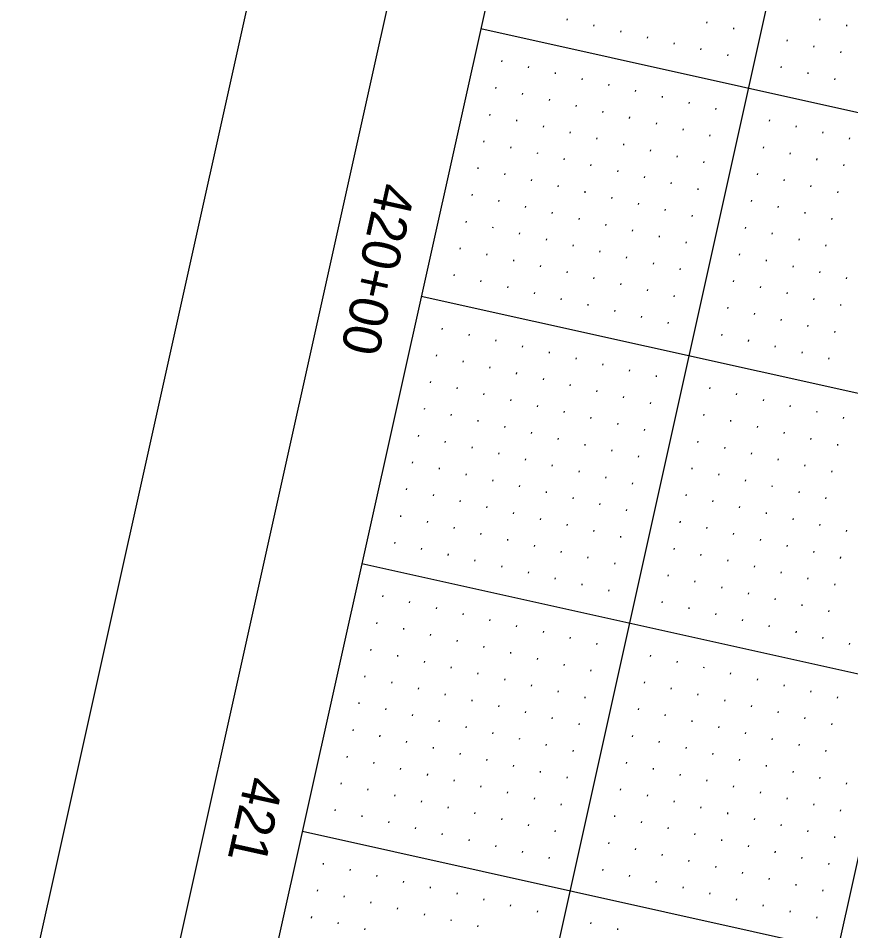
# Model space of a CAD drawing. Extents: x 2149268 to 2150830, y 142155 to 144285.
# Drawn here: x 2149420.1 to 2149571.9, y 142846.7 to 143013.1 of the extents above; entities that cross this region are included whole.
import ezdxf

# ---------------------------------------------------------------- set-up
doc = ezdxf.new("R2010")
doc.units = 0
for name, color, linetype in [('SHT_Plan_Profile_Sheet_Sta_Txt', 7, 'Continuous'), ('SHT_Plot_Shape_Half', 7, 'Continuous'), ('SHT_Profile_Grid_Major', 7, 'Continuous'), ('SHT_Profile_Grid_Minor', 7, 'Continuous'), ('SHT_Sheet_Border', 7, 'Continuous')]:
    doc.layers.add(name, color=color, linetype=linetype)

msp = doc.modelspace()

# ---------------------------------------------------------------- linework, layer by layer
at = {"layer": 'SHT_Plot_Shape_Half'}
msp.add_lwpolyline([(2150772.24, 143840.86), (2150403.25, 142181.39), (2149329.47, 142420.15), (2149698.47, 144079.62)], close=True, dxfattribs=at)
at = {"layer": 'SHT_Profile_Grid_Major'}
for p, q in [((2149767.6, 143964.37), (2149425.74, 142426.92)), ((2149816.41, 143953.52), (2149474.54, 142416.07)), ((2149504.45, 143011.27), (2149992.53, 142902.74)), ((2149493.59, 142962.46), (2149981.67, 142853.93)), ((2149482.74, 142913.65), (2149970.82, 142805.12)), ((2149471.89, 142864.84), (2149959.97, 142756.31))]:
    msp.add_line(p, q, dxfattribs=at)
at = {"layer": 'SHT_Profile_Grid_Minor'}
for p, q in [((2149520.2, 143013.01), (2149520.15, 143012.77)), ((2149525.08, 143011.93), (2149525.03, 143011.68)), ((2149545.69, 143012.47), (2149545.64, 143012.22)), ((2149566.3, 143013.01), (2149566.25, 143012.76)), ((2149571.18, 143011.92), (2149571.13, 143011.68)), ((2149529.96, 143010.84), (2149529.91, 143010.6)), ((2149550.57, 143011.38), (2149550.52, 143011.14)), ((2149534.84, 143009.76), (2149534.79, 143009.51)), ((2149539.73, 143008.67), (2149539.67, 143008.43)), ((2149560.33, 143009.21), (2149560.28, 143008.97)), ((2149544.61, 143007.59), (2149544.55, 143007.34)), ((2149565.21, 143008.13), (2149565.16, 143007.88)), ((2149570.1, 143007.04), (2149570.04, 143006.8)), ((2149508.27, 143005.42), (2149508.22, 143005.18)), ((2149549.49, 143006.5), (2149549.43, 143006.26)), ((2149513.15, 143004.34), (2149513.1, 143004.09)), ((2149559.25, 143004.33), (2149559.19, 143004.09)), ((2149518.03, 143003.25), (2149517.98, 143003.01)), ((2149522.91, 143002.17), (2149522.86, 143001.92)), ((2149564.13, 143003.25), (2149564.08, 143003)), ((2149569.01, 143002.16), (2149568.96, 143001.92)), ((2149507.18, 143000.54), (2149507.13, 143000.3)), ((2149527.79, 143001.08), (2149527.74, 143000.84)), ((2149512.07, 142999.46), (2149512.01, 142999.21)), ((2149532.67, 143000), (2149532.62, 142999.75)), ((2149537.55, 142998.91), (2149537.5, 142998.67)), ((2149516.95, 142998.37), (2149516.89, 142998.13)), ((2149521.83, 142997.29), (2149521.77, 142997.04)), ((2149542.44, 142997.83), (2149542.38, 142997.58)), ((2149506.1, 142995.66), (2149506.05, 142995.42)), ((2149526.71, 142996.2), (2149526.65, 142995.96)), ((2149547.32, 142996.74), (2149547.26, 142996.5)), ((2149510.98, 142994.58), (2149510.93, 142994.33)), ((2149515.86, 142993.49), (2149515.81, 142993.25)), ((2149531.59, 142995.12), (2149531.53, 142994.87)), ((2149536.47, 142994.03), (2149536.42, 142993.79)), ((2149557.08, 142994.57), (2149557.02, 142994.33)), ((2149520.74, 142992.4), (2149520.69, 142992.16)), ((2149541.35, 142992.94), (2149541.3, 142992.7)), ((2149546.23, 142991.86), (2149546.18, 142991.62)), ((2149561.96, 142993.48), (2149561.9, 142993.24)), ((2149566.84, 142992.4), (2149566.79, 142992.15)), ((2149505.01, 142990.78), (2149504.96, 142990.54)), ((2149525.62, 142991.32), (2149525.57, 142991.08)), ((2149530.5, 142990.23), (2149530.45, 142989.99)), ((2149571.72, 142991.31), (2149571.67, 142991.07)), ((2149509.9, 142989.69), (2149509.84, 142989.45)), ((2149514.78, 142988.61), (2149514.72, 142988.37)), ((2149535.38, 142989.15), (2149535.33, 142988.9)), ((2149555.99, 142989.69), (2149555.94, 142989.44)), ((2149560.87, 142988.6), (2149560.82, 142988.36)), ((2149519.66, 142987.52), (2149519.6, 142987.28)), ((2149540.27, 142988.06), (2149540.21, 142987.82)), ((2149545.15, 142986.98), (2149545.09, 142986.73)), ((2149565.75, 142987.52), (2149565.7, 142987.27)), ((2149503.93, 142985.9), (2149503.87, 142985.66)), ((2149524.54, 142986.44), (2149524.48, 142986.19)), ((2149529.42, 142985.35), (2149529.36, 142985.11)), ((2149570.64, 142986.43), (2149570.58, 142986.19)), ((2149508.81, 142984.81), (2149508.76, 142984.57)), ((2149513.69, 142983.73), (2149513.64, 142983.48)), ((2149534.3, 142984.27), (2149534.24, 142984.02)), ((2149554.91, 142984.81), (2149554.85, 142984.56)), ((2149559.79, 142983.72), (2149559.73, 142983.48)), ((2149518.57, 142982.64), (2149518.52, 142982.4)), ((2149539.18, 142983.18), (2149539.13, 142982.94)), ((2149544.06, 142982.1), (2149544.01, 142981.85)), ((2149564.67, 142982.64), (2149564.61, 142982.39)), ((2149502.84, 142981.02), (2149502.79, 142980.77)), ((2149523.45, 142981.56), (2149523.4, 142981.31)), ((2149528.33, 142980.47), (2149528.28, 142980.23)), ((2149569.55, 142981.55), (2149569.5, 142981.31)), ((2149507.72, 142979.93), (2149507.67, 142979.69)), ((2149512.61, 142978.85), (2149512.55, 142978.6)), ((2149533.21, 142979.39), (2149533.16, 142979.14)), ((2149553.82, 142979.93), (2149553.77, 142979.68)), ((2149558.7, 142978.84), (2149558.65, 142978.6)), ((2149517.49, 142977.76), (2149517.43, 142977.52)), ((2149538.09, 142978.3), (2149538.04, 142978.06)), ((2149542.98, 142977.22), (2149542.92, 142976.97)), ((2149563.58, 142977.76), (2149563.53, 142977.51)), ((2149501.76, 142976.14), (2149501.7, 142975.89)), ((2149522.37, 142976.68), (2149522.31, 142976.43)), ((2149527.25, 142975.59), (2149527.19, 142975.35)), ((2149568.46, 142976.67), (2149568.41, 142976.43)), ((2149506.64, 142975.05), (2149506.59, 142974.81)), ((2149511.52, 142973.97), (2149511.47, 142973.72)), ((2149532.13, 142974.51), (2149532.07, 142974.26)), ((2149552.74, 142975.05), (2149552.68, 142974.8)), ((2149557.62, 142973.96), (2149557.56, 142973.72)), ((2149516.4, 142972.88), (2149516.35, 142972.64)), ((2149537.01, 142973.42), (2149536.96, 142973.18)), ((2149541.89, 142972.34), (2149541.84, 142972.09)), ((2149562.5, 142972.88), (2149562.44, 142972.63)), ((2149500.67, 142971.26), (2149500.62, 142971.01)), ((2149521.28, 142971.8), (2149521.23, 142971.55)), ((2149526.16, 142970.71), (2149526.11, 142970.47)), ((2149567.38, 142971.79), (2149567.33, 142971.55)), ((2149505.55, 142970.17), (2149505.5, 142969.93)), ((2149510.43, 142969.09), (2149510.38, 142968.84)), ((2149531.04, 142969.63), (2149530.99, 142969.38)), ((2149535.92, 142968.54), (2149535.87, 142968.3)), ((2149551.65, 142970.17), (2149551.6, 142969.92)), ((2149556.53, 142969.08), (2149556.48, 142968.84)), ((2149515.32, 142968), (2149515.26, 142967.76)), ((2149520.2, 142966.92), (2149520.14, 142966.67)), ((2149540.8, 142967.46), (2149540.75, 142967.21)), ((2149561.41, 142967.99), (2149561.36, 142967.75)), ((2149566.29, 142966.91), (2149566.24, 142966.67)), ((2149499.59, 142966.38), (2149499.53, 142966.13)), ((2149504.47, 142965.29), (2149504.41, 142965.05)), ((2149525.08, 142965.83), (2149525.02, 142965.59)), ((2149550.57, 142965.28), (2149550.51, 142965.04)), ((2149571.17, 142965.82), (2149571.12, 142965.58)), ((2149509.35, 142964.21), (2149509.3, 142963.96)), ((2149529.96, 142964.75), (2149529.9, 142964.5)), ((2149534.84, 142963.66), (2149534.78, 142963.42)), ((2149555.45, 142964.2), (2149555.39, 142963.96)), ((2149514.23, 142963.12), (2149514.18, 142962.88)), ((2149519.11, 142962.03), (2149519.06, 142961.79)), ((2149539.72, 142962.57), (2149539.67, 142962.33)), ((2149560.33, 142963.11), (2149560.27, 142962.87)), ((2149565.21, 142962.03), (2149565.15, 142961.78)), ((2149523.99, 142960.95), (2149523.94, 142960.71)), ((2149549.48, 142960.4), (2149549.43, 142960.16)), ((2149570.09, 142960.94), (2149570.04, 142960.7)), ((2149528.87, 142959.86), (2149528.82, 142959.62)), ((2149533.75, 142958.78), (2149533.7, 142958.53)), ((2149554.36, 142959.32), (2149554.31, 142959.07)), ((2149538.63, 142957.69), (2149538.58, 142957.45)), ((2149559.24, 142958.23), (2149559.19, 142957.99)), ((2149564.12, 142957.15), (2149564.07, 142956.9)), ((2149497.42, 142956.61), (2149497.36, 142956.37)), ((2149502.3, 142955.53), (2149502.24, 142955.28)), ((2149548.4, 142955.52), (2149548.34, 142955.28)), ((2149569, 142956.06), (2149568.95, 142955.82)), ((2149507.18, 142954.44), (2149507.12, 142954.2)), ((2149553.28, 142954.44), (2149553.22, 142954.19)), ((2149512.06, 142953.36), (2149512.01, 142953.11)), ((2149516.94, 142952.27), (2149516.89, 142952.03)), ((2149558.16, 142953.35), (2149558.1, 142953.11)), ((2149563.04, 142952.27), (2149562.98, 142952.02)), ((2149496.33, 142951.73), (2149496.28, 142951.49)), ((2149501.21, 142950.65), (2149501.16, 142950.4)), ((2149521.82, 142951.19), (2149521.77, 142950.94)), ((2149567.92, 142951.18), (2149567.86, 142950.94)), ((2149506.09, 142949.56), (2149506.04, 142949.32)), ((2149526.7, 142950.1), (2149526.65, 142949.86)), ((2149531.58, 142949.02), (2149531.53, 142948.77)), ((2149510.97, 142948.48), (2149510.92, 142948.23)), ((2149515.86, 142947.39), (2149515.8, 142947.15)), ((2149536.46, 142947.93), (2149536.41, 142947.69)), ((2149495.25, 142946.85), (2149495.19, 142946.61)), ((2149500.13, 142945.77), (2149500.07, 142945.52)), ((2149520.74, 142946.31), (2149520.68, 142946.06)), ((2149525.62, 142945.22), (2149525.56, 142944.98)), ((2149546.23, 142945.76), (2149546.17, 142945.52)), ((2149505.01, 142944.68), (2149504.95, 142944.44)), ((2149509.89, 142943.6), (2149509.83, 142943.35)), ((2149530.5, 142944.14), (2149530.44, 142943.89)), ((2149551.11, 142944.68), (2149551.05, 142944.43)), ((2149555.99, 142943.59), (2149555.93, 142943.35)), ((2149494.16, 142941.97), (2149494.11, 142941.73)), ((2149514.77, 142942.51), (2149514.72, 142942.27)), ((2149535.38, 142943.05), (2149535.32, 142942.81)), ((2149560.87, 142942.51), (2149560.81, 142942.26)), ((2149499.04, 142940.89), (2149498.99, 142940.64)), ((2149519.65, 142941.43), (2149519.6, 142941.18)), ((2149524.53, 142940.34), (2149524.48, 142940.1)), ((2149545.14, 142940.88), (2149545.09, 142940.64)), ((2149565.75, 142941.42), (2149565.69, 142941.18)), ((2149570.63, 142940.34), (2149570.57, 142940.09)), ((2149503.92, 142939.8), (2149503.87, 142939.56)), ((2149508.8, 142938.72), (2149508.75, 142938.47)), ((2149529.41, 142939.26), (2149529.36, 142939.01)), ((2149550.02, 142939.8), (2149549.97, 142939.55)), ((2149554.9, 142938.71), (2149554.85, 142938.47)), ((2149493.08, 142937.09), (2149493.02, 142936.85)), ((2149513.68, 142937.63), (2149513.63, 142937.39)), ((2149534.29, 142938.17), (2149534.24, 142937.93)), ((2149559.78, 142937.62), (2149559.73, 142937.38)), ((2149497.96, 142936.01), (2149497.9, 142935.76)), ((2149518.57, 142936.55), (2149518.51, 142936.3)), ((2149523.45, 142935.46), (2149523.39, 142935.22)), ((2149544.05, 142936), (2149544, 142935.76)), ((2149564.66, 142936.54), (2149564.61, 142936.3)), ((2149569.54, 142935.45), (2149569.49, 142935.21)), ((2149502.84, 142934.92), (2149502.78, 142934.68)), ((2149507.72, 142933.84), (2149507.66, 142933.59)), ((2149528.33, 142934.37), (2149528.27, 142934.13)), ((2149548.94, 142934.91), (2149548.88, 142934.67)), ((2149553.82, 142933.83), (2149553.76, 142933.59)), ((2149491.99, 142932.21), (2149491.94, 142931.97)), ((2149512.6, 142932.75), (2149512.55, 142932.51)), ((2149533.21, 142933.29), (2149533.15, 142933.05)), ((2149558.7, 142932.74), (2149558.64, 142932.5)), ((2149496.87, 142931.13), (2149496.82, 142930.88)), ((2149517.48, 142931.66), (2149517.43, 142931.42)), ((2149522.36, 142930.58), (2149522.31, 142930.34)), ((2149542.97, 142931.12), (2149542.92, 142930.88)), ((2149563.58, 142931.66), (2149563.52, 142931.41)), ((2149568.46, 142930.57), (2149568.4, 142930.33)), ((2149501.75, 142930.04), (2149501.7, 142929.8)), ((2149506.63, 142928.95), (2149506.58, 142928.71)), ((2149527.24, 142929.49), (2149527.19, 142929.25)), ((2149547.85, 142930.03), (2149547.8, 142929.79)), ((2149552.73, 142928.95), (2149552.68, 142928.7)), ((2149490.91, 142927.33), (2149490.85, 142927.09)), ((2149511.51, 142927.87), (2149511.46, 142927.63)), ((2149532.12, 142928.41), (2149532.07, 142928.16)), ((2149557.61, 142927.86), (2149557.56, 142927.62)), ((2149495.79, 142926.24), (2149495.73, 142926)), ((2149516.39, 142926.78), (2149516.34, 142926.54)), ((2149521.28, 142925.7), (2149521.22, 142925.45)), ((2149541.88, 142926.24), (2149541.83, 142925.99)), ((2149562.49, 142926.78), (2149562.44, 142926.53)), ((2149567.37, 142925.69), (2149567.32, 142925.45)), ((2149500.67, 142925.16), (2149500.61, 142924.91)), ((2149505.55, 142924.07), (2149505.49, 142923.83)), ((2149526.16, 142924.61), (2149526.1, 142924.37)), ((2149546.76, 142925.15), (2149546.71, 142924.91)), ((2149551.65, 142924.07), (2149551.59, 142923.82)), ((2149489.82, 142922.45), (2149489.77, 142922.2)), ((2149510.43, 142922.99), (2149510.37, 142922.74)), ((2149531.04, 142923.53), (2149530.98, 142923.28)), ((2149556.53, 142922.98), (2149556.47, 142922.74)), ((2149494.7, 142921.36), (2149494.65, 142921.12)), ((2149499.58, 142920.28), (2149499.53, 142920.03)), ((2149515.31, 142921.9), (2149515.26, 142921.66)), ((2149520.19, 142920.82), (2149520.14, 142920.57)), ((2149540.8, 142921.36), (2149540.74, 142921.11)), ((2149545.68, 142920.27), (2149545.63, 142920.03)), ((2149561.41, 142921.9), (2149561.35, 142921.65)), ((2149566.29, 142920.81), (2149566.23, 142920.57)), ((2149504.46, 142919.19), (2149504.41, 142918.95)), ((2149525.07, 142919.73), (2149525.02, 142919.49)), ((2149529.95, 142918.65), (2149529.9, 142918.4)), ((2149550.56, 142919.19), (2149550.51, 142918.94)), ((2149571.17, 142919.73), (2149571.11, 142919.48)), ((2149488.74, 142917.57), (2149488.68, 142917.32)), ((2149509.34, 142918.11), (2149509.29, 142917.86)), ((2149514.22, 142917.02), (2149514.17, 142916.78)), ((2149555.44, 142918.1), (2149555.39, 142917.86)), ((2149560.32, 142917.02), (2149560.27, 142916.77)), ((2149493.62, 142916.48), (2149493.56, 142916.24)), ((2149498.5, 142915.4), (2149498.44, 142915.15)), ((2149519.11, 142915.94), (2149519.05, 142915.69)), ((2149539.71, 142916.48), (2149539.66, 142916.23)), ((2149544.59, 142915.39), (2149544.54, 142915.15)), ((2149565.2, 142915.93), (2149565.15, 142915.69)), ((2149503.38, 142914.31), (2149503.32, 142914.07)), ((2149523.99, 142914.85), (2149523.93, 142914.61)), ((2149528.87, 142913.77), (2149528.81, 142913.52)), ((2149549.48, 142914.31), (2149549.42, 142914.06)), ((2149570.08, 142914.85), (2149570.03, 142914.6)), ((2149508.26, 142913.23), (2149508.2, 142912.98)), ((2149513.14, 142912.14), (2149513.08, 142911.9)), ((2149554.36, 142913.22), (2149554.3, 142912.98)), ((2149559.24, 142912.14), (2149559.18, 142911.89)), ((2149518.02, 142911.06), (2149517.97, 142910.81)), ((2149538.63, 142911.6), (2149538.57, 142911.35)), ((2149543.51, 142910.51), (2149543.45, 142910.27)), ((2149564.12, 142911.05), (2149564.06, 142910.81)), ((2149522.9, 142909.97), (2149522.85, 142909.73)), ((2149527.78, 142908.89), (2149527.73, 142908.64)), ((2149548.39, 142909.43), (2149548.34, 142909.18)), ((2149569, 142909.97), (2149568.94, 142909.72)), ((2149486.56, 142907.81), (2149486.51, 142907.56)), ((2149553.27, 142908.34), (2149553.22, 142908.1)), ((2149558.15, 142907.25), (2149558.1, 142907.01)), ((2149491.45, 142906.72), (2149491.39, 142906.48)), ((2149496.33, 142905.64), (2149496.27, 142905.39)), ((2149537.54, 142906.72), (2149537.49, 142906.47)), ((2149542.42, 142905.63), (2149542.37, 142905.39)), ((2149563.03, 142906.17), (2149562.98, 142905.93)), ((2149501.21, 142904.55), (2149501.15, 142904.31)), ((2149547.3, 142904.54), (2149547.25, 142904.3)), ((2149567.91, 142905.08), (2149567.86, 142904.84)), ((2149485.48, 142902.93), (2149485.43, 142902.68)), ((2149506.09, 142903.47), (2149506.03, 142903.22)), ((2149510.97, 142902.38), (2149510.91, 142902.14)), ((2149552.19, 142903.46), (2149552.13, 142903.22)), ((2149557.07, 142902.37), (2149557.01, 142902.13)), ((2149490.36, 142901.84), (2149490.31, 142901.6)), ((2149495.24, 142900.75), (2149495.19, 142900.51)), ((2149515.85, 142901.29), (2149515.8, 142901.05)), ((2149561.95, 142901.29), (2149561.89, 142901.04)), ((2149500.12, 142899.67), (2149500.07, 142899.43)), ((2149520.73, 142900.21), (2149520.68, 142899.97)), ((2149525.61, 142899.12), (2149525.56, 142898.88)), ((2149566.83, 142900.2), (2149566.77, 142899.96)), ((2149571.71, 142899.12), (2149571.65, 142898.87)), ((2149484.39, 142898.04), (2149484.34, 142897.8)), ((2149489.27, 142896.96), (2149489.22, 142896.72)), ((2149505, 142898.58), (2149504.95, 142898.34)), ((2149509.88, 142897.5), (2149509.83, 142897.26)), ((2149535.37, 142896.95), (2149535.32, 142896.71)), ((2149494.16, 142895.87), (2149494.1, 142895.63)), ((2149514.76, 142896.41), (2149514.71, 142896.17)), ((2149519.64, 142895.33), (2149519.59, 142895.08)), ((2149540.25, 142895.87), (2149540.2, 142895.62)), ((2149499.04, 142894.79), (2149498.98, 142894.54)), ((2149503.92, 142893.7), (2149503.86, 142893.46)), ((2149524.53, 142894.24), (2149524.47, 142894)), ((2149545.13, 142894.78), (2149545.08, 142894.54)), ((2149550.01, 142893.7), (2149549.96, 142893.45)), ((2149483.31, 142893.16), (2149483.25, 142892.92)), ((2149488.19, 142892.08), (2149488.14, 142891.83)), ((2149508.8, 142892.62), (2149508.74, 142892.37)), ((2149534.29, 142892.07), (2149534.23, 142891.83)), ((2149554.9, 142892.61), (2149554.84, 142892.37)), ((2149493.07, 142890.99), (2149493.02, 142890.75)), ((2149513.68, 142891.53), (2149513.62, 142891.29)), ((2149518.56, 142890.45), (2149518.51, 142890.2)), ((2149539.17, 142890.99), (2149539.11, 142890.74)), ((2149559.78, 142891.53), (2149559.72, 142891.28)), ((2149564.66, 142890.44), (2149564.6, 142890.2)), ((2149497.95, 142889.91), (2149497.9, 142889.66)), ((2149502.83, 142888.82), (2149502.78, 142888.58)), ((2149523.44, 142889.36), (2149523.39, 142889.12)), ((2149544.05, 142889.9), (2149543.99, 142889.66)), ((2149548.93, 142888.82), (2149548.88, 142888.57)), ((2149569.54, 142889.36), (2149569.48, 142889.11)), ((2149482.22, 142888.28), (2149482.17, 142888.04)), ((2149487.1, 142887.2), (2149487.05, 142886.95)), ((2149507.71, 142887.74), (2149507.66, 142887.49)), ((2149533.2, 142887.19), (2149533.15, 142886.95)), ((2149553.81, 142887.73), (2149553.76, 142887.49)), ((2149491.99, 142886.11), (2149491.93, 142885.87)), ((2149512.59, 142886.65), (2149512.54, 142886.41)), ((2149517.47, 142885.57), (2149517.42, 142885.32)), ((2149538.08, 142886.11), (2149538.03, 142885.86)), ((2149558.69, 142886.65), (2149558.64, 142886.4)), ((2149563.57, 142885.56), (2149563.52, 142885.32)), ((2149496.87, 142885.03), (2149496.81, 142884.78)), ((2149501.75, 142883.94), (2149501.69, 142883.7)), ((2149522.36, 142884.48), (2149522.3, 142884.24)), ((2149542.96, 142885.02), (2149542.91, 142884.78)), ((2149547.84, 142883.94), (2149547.79, 142883.69)), ((2149568.45, 142884.48), (2149568.4, 142884.23)), ((2149481.14, 142883.4), (2149481.08, 142883.16)), ((2149486.02, 142882.32), (2149485.96, 142882.07)), ((2149506.63, 142882.86), (2149506.57, 142882.61)), ((2149532.12, 142882.31), (2149532.06, 142882.07)), ((2149552.73, 142882.85), (2149552.67, 142882.61)), ((2149490.9, 142881.23), (2149490.85, 142880.99)), ((2149511.51, 142881.77), (2149511.45, 142881.53)), ((2149516.39, 142880.69), (2149516.33, 142880.44)), ((2149537, 142881.23), (2149536.94, 142880.98)), ((2149557.61, 142881.77), (2149557.55, 142881.52)), ((2149562.49, 142880.68), (2149562.43, 142880.44)), ((2149495.78, 142880.15), (2149495.73, 142879.9)), ((2149500.66, 142879.06), (2149500.61, 142878.82)), ((2149521.27, 142879.6), (2149521.22, 142879.36)), ((2149541.88, 142880.14), (2149541.82, 142879.9)), ((2149546.76, 142879.06), (2149546.7, 142878.81)), ((2149567.37, 142879.6), (2149567.31, 142879.35)), ((2149480.05, 142878.52), (2149480, 142878.28)), ((2149484.93, 142877.44), (2149484.88, 142877.19)), ((2149505.54, 142877.98), (2149505.49, 142877.73)), ((2149531.03, 142877.43), (2149530.98, 142877.19)), ((2149551.64, 142877.97), (2149551.59, 142877.73)), ((2149489.81, 142876.35), (2149489.76, 142876.11)), ((2149510.42, 142876.89), (2149510.37, 142876.65)), ((2149515.3, 142875.81), (2149515.25, 142875.56)), ((2149535.91, 142876.35), (2149535.86, 142876.1)), ((2149556.52, 142876.88), (2149556.47, 142876.64)), ((2149561.4, 142875.8), (2149561.35, 142875.56)), ((2149478.97, 142873.64), (2149478.91, 142873.4)), ((2149494.7, 142875.27), (2149494.64, 142875.02)), ((2149499.58, 142874.18), (2149499.52, 142873.94)), ((2149520.18, 142874.72), (2149520.13, 142874.48)), ((2149540.79, 142875.26), (2149540.74, 142875.02)), ((2149545.67, 142874.17), (2149545.62, 142873.93)), ((2149566.28, 142874.71), (2149566.23, 142874.47)), ((2149483.85, 142872.56), (2149483.79, 142872.31)), ((2149504.46, 142873.1), (2149504.4, 142872.85)), ((2149509.34, 142872.01), (2149509.28, 142871.77)), ((2149529.95, 142872.55), (2149529.89, 142872.31)), ((2149550.55, 142873.09), (2149550.5, 142872.85)), ((2149555.44, 142872), (2149555.38, 142871.76)), ((2149571.16, 142873.63), (2149571.11, 142873.38)), ((2149488.73, 142871.47), (2149488.67, 142871.23)), ((2149493.61, 142870.38), (2149493.56, 142870.14)), ((2149514.22, 142870.92), (2149514.16, 142870.68)), ((2149534.83, 142871.46), (2149534.77, 142871.22)), ((2149539.71, 142870.38), (2149539.65, 142870.13)), ((2149560.32, 142870.92), (2149560.26, 142870.67)), ((2149477.88, 142868.76), (2149477.83, 142868.52)), ((2149498.49, 142869.3), (2149498.44, 142869.06)), ((2149519.1, 142869.84), (2149519.04, 142869.6)), ((2149544.59, 142869.29), (2149544.53, 142869.05)), ((2149565.2, 142869.83), (2149565.14, 142869.59)), ((2149570.08, 142868.75), (2149570.02, 142868.5)), ((2149482.76, 142867.67), (2149482.71, 142867.43)), ((2149503.37, 142868.21), (2149503.32, 142867.97)), ((2149508.25, 142867.13), (2149508.2, 142866.89)), ((2149528.86, 142867.67), (2149528.81, 142867.42)), ((2149549.47, 142868.21), (2149549.42, 142867.96)), ((2149554.35, 142867.12), (2149554.3, 142866.88)), ((2149487.64, 142866.59), (2149487.59, 142866.35)), ((2149492.52, 142865.5), (2149492.47, 142865.26)), ((2149513.13, 142866.04), (2149513.08, 142865.8)), ((2149533.74, 142866.58), (2149533.69, 142866.34)), ((2149538.62, 142865.5), (2149538.57, 142865.25)), ((2149559.23, 142866.04), (2149559.18, 142865.79)), ((2149497.41, 142864.42), (2149497.35, 142864.17)), ((2149518.01, 142864.96), (2149517.96, 142864.71)), ((2149543.5, 142864.41), (2149543.45, 142864.17)), ((2149564.11, 142864.95), (2149564.06, 142864.71)), ((2149568.99, 142863.87), (2149568.94, 142863.62)), ((2149502.29, 142863.33), (2149502.23, 142863.09)), ((2149507.17, 142862.25), (2149507.11, 142862)), ((2149527.78, 142862.79), (2149527.72, 142862.54)), ((2149548.38, 142863.33), (2149548.33, 142863.08)), ((2149553.26, 142862.24), (2149553.21, 142862)), ((2149512.05, 142861.16), (2149511.99, 142860.92)), ((2149532.66, 142861.7), (2149532.6, 142861.46)), ((2149537.54, 142860.62), (2149537.48, 142860.37)), ((2149558.15, 142861.16), (2149558.09, 142860.91)), ((2149475.71, 142859), (2149475.66, 142858.75)), ((2149516.93, 142860.08), (2149516.87, 142859.83)), ((2149542.42, 142859.53), (2149542.36, 142859.29)), ((2149563.03, 142860.07), (2149562.97, 142859.83)), ((2149567.91, 142858.99), (2149567.85, 142858.74)), ((2149480.59, 142857.91), (2149480.54, 142857.67)), ((2149526.69, 142857.91), (2149526.64, 142857.66)), ((2149547.3, 142858.45), (2149547.24, 142858.2)), ((2149552.18, 142857.36), (2149552.13, 142857.12)), ((2149485.47, 142856.83), (2149485.42, 142856.58)), ((2149490.35, 142855.74), (2149490.3, 142855.5)), ((2149531.57, 142856.82), (2149531.52, 142856.58)), ((2149536.45, 142855.74), (2149536.4, 142855.49)), ((2149557.06, 142856.28), (2149557.01, 142856.03)), ((2149474.63, 142854.12), (2149474.57, 142853.87)), ((2149495.23, 142854.66), (2149495.18, 142854.41)), ((2149541.33, 142854.65), (2149541.28, 142854.41)), ((2149561.94, 142855.19), (2149561.89, 142854.95)), ((2149566.82, 142854.11), (2149566.77, 142853.86)), ((2149479.51, 142853.03), (2149479.45, 142852.79)), ((2149500.12, 142853.57), (2149500.06, 142853.33)), ((2149505, 142852.49), (2149504.94, 142852.24)), ((2149546.21, 142853.57), (2149546.16, 142853.32)), ((2149551.09, 142852.48), (2149551.04, 142852.24)), ((2149484.39, 142851.95), (2149484.33, 142851.7)), ((2149489.27, 142850.86), (2149489.21, 142850.62)), ((2149509.88, 142851.4), (2149509.82, 142851.16)), ((2149555.98, 142851.4), (2149555.92, 142851.15)), ((2149473.54, 142849.24), (2149473.49, 142848.99)), ((2149494.15, 142849.78), (2149494.1, 142849.53)), ((2149499.03, 142848.69), (2149498.98, 142848.45)), ((2149514.76, 142850.32), (2149514.7, 142850.07)), ((2149560.86, 142850.31), (2149560.8, 142850.07)), ((2149565.74, 142849.23), (2149565.68, 142848.98)), ((2149478.42, 142848.15), (2149478.37, 142847.91)), ((2149483.3, 142847.07), (2149483.25, 142846.82)), ((2149503.91, 142847.61), (2149503.86, 142847.36)), ((2149524.52, 142848.15), (2149524.47, 142847.9)), ((2149529.4, 142847.06), (2149529.35, 142846.82))]:
    msp.add_line(p, q, dxfattribs=at)
at = {"layer": 'SHT_Sheet_Border'}
msp.add_line((2149718.79, 143975.22), (2149433.9, 142694.01), dxfattribs=at)
msp.add_lwpolyline([(2150726.67, 143751.11), (2150384.81, 142213.66), (2149359.84, 142441.57), (2149701.71, 143979.02)], close=True, dxfattribs=at)

# ---------------------------------------------------------------- texts
at = {"layer": 'SHT_Plan_Profile_Sheet_Sta_Txt'}
for s, p in [('420+00', (2149485.71, 142983.43)), ('421', (2149461.63, 142875.13))]:
    msp.add_text(s, height=7, rotation=257.4638, dxfattribs=at).set_placement(p)

doc.saveas('drawing.dxf')
